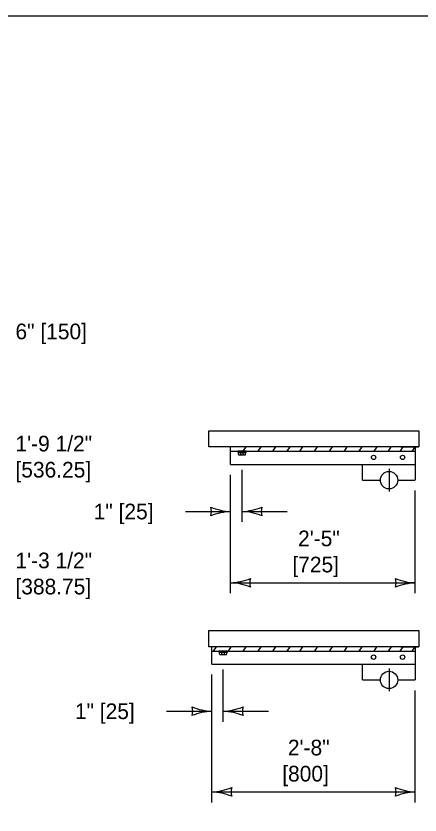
# Model space of a CAD drawing. Extents: x 49991.4 to 50021, y 49987.6 to 50011.4.
# Drawn here: x 50007.212 to 50008.76, y 49995.939 to 49998.999 of the extents above; entities that cross this region are included whole.
import ezdxf

# ---------------------------------------------------------------- set-up
doc = ezdxf.new("R2010")
doc.units = 0
for name, color, linetype in [('Level 1', 7, 'Continuous'), ('Level 2', 7, 'Continuous'), ('Level 3', 7, 'Continuous'), ('Level 5', 7, 'Continuous')]:
    doc.layers.add(name, color=color, linetype=linetype)

msp = doc.modelspace()

# ---------------------------------------------------------------- linework, layer by layer
at = {"layer": 'Level 1'}
for p, q in [((50007.9502, 49997.3487), (50007.9502, 49997.4108)), ((50007.9502, 49997.4108), (50008.7546, 49997.4108)), ((50008.7546, 49997.4108), (50008.7546, 49997.3487)), ((50008.7546, 49997.3487), (50007.9502, 49997.3487)), ((50008.7546, 49997.3487), (50008.0344, 49997.3487)), ((50008.0344, 49997.2817), (50008.0344, 49997.3487)), ((50008.0344, 49997.3319), (50008.6198, 49997.3319)), ((50008.0825, 49997.3319), (50008.0939, 49997.3487)), ((50008.1394, 49997.3319), (50008.1508, 49997.3487)), ((50008.1962, 49997.3319), (50008.2076, 49997.3487)), ((50008.2511, 49997.3319), (50008.2625, 49997.3487)), ((50008.2992, 49997.3319), (50008.3106, 49997.3487)), ((50008.3561, 49997.3319), (50008.3675, 49997.3487)), ((50008.4129, 49997.3319), (50008.4243, 49997.3487)), ((50008.4698, 49997.3319), (50008.4812, 49997.3487)), ((50008.5268, 49997.3319), (50008.5381, 49997.3487)), ((50008.5836, 49997.3319), (50008.5949, 49997.3487)), ((50008.6198, 49997.3319), (50008.7415, 49997.3319)), ((50008.6385, 49997.3319), (50008.6497, 49997.3485)), ((50008.6833, 49997.3318), (50008.6947, 49997.3487)), ((50008.6865, 49997.3487), (50008.7543, 49997.3487)), ((50008.7295, 49997.3318), (50008.7409, 49997.3487)), ((50008.7415, 49997.3487), (50008.7415, 49997.2221)), ((50008.064, 49997.3209), (50008.064, 49997.3272)), ((50008.0666, 49997.3183), (50008.0892, 49997.3183)), ((50008.0732, 49997.3208), (50008.0732, 49997.3272)), ((50008.0824, 49997.3208), (50008.0824, 49997.3272)), ((50008.0917, 49997.3209), (50008.0917, 49997.3272)), ((50008.0344, 49997.2817), (50008.5388, 49997.2817)), ((50008.5388, 49997.2214), (50008.5388, 49997.2817)), ((50008.5388, 49997.2817), (50008.7415, 49997.2817)), ((50008.5388, 49997.2214), (50008.6068, 49997.2214)), ((50008.6745, 49997.2214), (50008.7415, 49997.2214)), ((50007.9502, 49996.6459), (50008.7546, 49996.6459)), ((50007.9502, 49996.5837), (50007.9502, 49996.6459)), ((50008.7546, 49996.6459), (50008.7546, 49996.5837)), ((50008.7546, 49996.5837), (50007.9502, 49996.5837)), ((50007.9624, 49996.5168), (50007.9624, 49996.5837)), ((50007.9624, 49996.567), (50008.6198, 49996.567)), ((50007.9689, 49996.567), (50007.9801, 49996.5837)), ((50008.0257, 49996.567), (50008.0369, 49996.5837)), ((50008.0826, 49996.567), (50008.0938, 49996.5837)), ((50008.1395, 49996.567), (50008.1507, 49996.5837)), ((50008.1963, 49996.567), (50008.2075, 49996.5837)), ((50008.2512, 49996.567), (50008.2625, 49996.5837)), ((50008.2993, 49996.567), (50008.3105, 49996.5837)), ((50008.3562, 49996.567), (50008.3674, 49996.5837)), ((50008.413, 49996.567), (50008.4242, 49996.5837)), ((50008.4699, 49996.567), (50008.4811, 49996.5837)), ((50008.5268, 49996.567), (50008.538, 49996.5837)), ((50008.5836, 49996.567), (50008.5948, 49996.5837)), ((50008.6198, 49996.567), (50008.7415, 49996.567)), ((50008.6385, 49996.567), (50008.6498, 49996.5837)), ((50008.6835, 49996.567), (50008.6948, 49996.5837)), ((50008.6866, 49996.5837), (50008.7543, 49996.5837)), ((50008.7296, 49996.567), (50008.7415, 49996.5837)), ((50008.7415, 49996.5837), (50008.7415, 49996.4572)), ((50007.992, 49996.556), (50007.992, 49996.5623)), ((50007.9946, 49996.5534), (50008.0172, 49996.5534)), ((50008.0012, 49996.5559), (50008.0012, 49996.5623)), ((50008.0104, 49996.5559), (50008.0104, 49996.5623)), ((50008.0197, 49996.556), (50008.0197, 49996.5623)), ((50007.9624, 49996.5168), (50008.5389, 49996.5168)), ((50008.5389, 49996.4564), (50008.5389, 49996.5168)), ((50008.5389, 49996.5168), (50008.7415, 49996.5168)), ((50008.5389, 49996.4564), (50008.6069, 49996.4564)), ((50008.6745, 49996.4564), (50008.7415, 49996.4564))]:
    msp.add_line(p, q, dxfattribs=at)
for points in [[(49999.3835, 49998.9992), (50016.7501, 49998.9992), (50016.7501, 49987.7988), (49999.3835, 49987.7988)], [(50008.0613, 49997.3319), (50008.0613, 49997.3272), (50008.0941, 49997.3272), (50008.0941, 49997.3319)], [(50007.9893, 49996.567), (50007.9893, 49996.5623), (50008.0221, 49996.5623), (50008.0221, 49996.567)]]:
    msp.add_lwpolyline(points, close=True, dxfattribs=at)
for centre, radius in [((50008.5819, 49997.3087), 0.00843), ((50008.693, 49997.3087), 0.00843), ((50008.641, 49997.2214), 0.0333), ((50008.5819, 49996.5437), 0.00843), ((50008.693, 49996.5437), 0.00843), ((50008.6411, 49996.4564), 0.0333)]:
    msp.add_circle(centre, radius, dxfattribs=at)
for centre, start, end in [((50008.0666, 49997.3208), 180, 270), ((50008.0707, 49997.3208), 270, 0), ((50008.0758, 49997.3208), 180, 270), ((50008.0799, 49997.3208), 270, 0), ((50008.085, 49997.3208), 180, 270), ((50008.0891, 49997.3208), 270, 0), ((50007.9946, 49996.5559), 180, 270), ((50007.9987, 49996.5559), 270, 0), ((50008.0038, 49996.5559), 180, 270), ((50008.0079, 49996.5559), 270, 0), ((50008.013, 49996.5559), 180, 270), ((50008.0171, 49996.5559), 270, 0)]:
    msp.add_arc(centre, 0.00257, start, end, dxfattribs=at)
at = {"layer": 'Level 3'}
for p, q in [((50008.0344, 49996.7883), (50008.0344, 49997.2417)), ((50008.0779, 49997.0614), (50008.0779, 49997.2613)), ((50008.7415, 49996.7883), (50008.7415, 49997.1814)), ((50007.861, 49997.1014), (50008.0344, 49997.1014)), ((50008.0779, 49997.1014), (50008.2513, 49997.1014)), ((50008.0344, 49996.8283), (50008.7415, 49996.8283)), ((50007.9624, 49995.9874), (50007.9624, 49996.4768)), ((50008.0059, 49996.2964), (50008.0059, 49996.4964)), ((50008.7415, 49995.9874), (50008.7415, 49996.4164)), ((50007.789, 49996.3364), (50007.9624, 49996.3364)), ((50008.0059, 49996.3364), (50008.1793, 49996.3364)), ((50007.9624, 49996.0274), (50008.7415, 49996.0274))]:
    msp.add_line(p, q, dxfattribs=at)
for centre, radius, start, end in [((50008.0436, 49997.3235), 0.2223, 247.456, 267.6395), ((50007.9062, 49997.1014), 0.0548, 342.1388, 17.8612), ((50008.0664, 49997.3341), 0.233, 272.8273, 292.0772), ((50008.2061, 49997.1014), 0.0548, 162.1388, 197.8612), ((50008.0459, 49996.8687), 0.233, 92.8273, 112.0772), ((50008.0687, 49996.8793), 0.2223, 67.456, 87.6395), ((50008.0229, 49997.061), 0.233, 272.8273, 292.0772), ((50008.1626, 49996.8283), 0.0548, 162.1388, 197.8612), ((50008.7507, 49997.0504), 0.2223, 247.456, 267.6395), ((50008.6133, 49996.8283), 0.0548, 342.1388, 17.8612), ((50008.0252, 49996.6061), 0.2223, 67.456, 87.6395), ((50008.753, 49996.5956), 0.233, 92.8273, 112.0772), ((50007.9716, 49996.5585), 0.2223, 247.456, 267.6395), ((50007.8342, 49996.3364), 0.0548, 342.1388, 17.8612), ((50007.9944, 49996.5691), 0.233, 272.8273, 292.0772), ((50008.1341, 49996.3364), 0.0548, 162.1388, 197.8612), ((50007.9739, 49996.1037), 0.233, 92.8273, 112.0772), ((50007.9967, 49996.1143), 0.2223, 67.456, 87.6395), ((50007.9509, 49996.2601), 0.233, 272.8273, 292.0772), ((50008.0906, 49996.0274), 0.0548, 162.1388, 197.8612), ((50008.7507, 49996.2496), 0.2223, 247.456, 267.6395), ((50008.6133, 49996.0274), 0.0548, 342.1388, 17.8612), ((50007.9532, 49995.8053), 0.2223, 67.456, 87.6395), ((50008.753, 49995.7947), 0.233, 92.8273, 112.0772)]:
    msp.add_arc(centre, radius, start, end, dxfattribs=at)
at = {"layer": 'Level 5'}
for p, q in [((50008.6409, 49997.2646), (50008.6409, 49997.1781)), ((50008.641, 49996.4997), (50008.641, 49996.4132))]:
    msp.add_line(p, q, dxfattribs=at)

# ---------------------------------------------------------------- texts
at = {"layer": 'Level 2'}
for s, p in [('6" [150]', (50007.2102, 49997.761)), ('1\'-9 1/2"', (50007.2102, 49997.3315)), ('[536.25]', (50007.2102, 49997.2315)), ('1" [25]', (50007.5099, 49997.0714)), ('2\'-5"', (50008.2926, 49996.9683)), ('1\'-3 1/2"', (50007.2102, 49996.884)), ('[725]', (50008.2708, 49996.8683)), ('[388.75]', (50007.2102, 49996.784)), ('1" [25]', (50007.4379, 49996.3064)), ('2\'-8"', (50008.2536, 49996.1674)), ('[800]', (50008.2319, 49996.0674))]:
    msp.add_text(s, height=0.06, dxfattribs=at).set_placement(p)

doc.saveas('drawing.dxf')
